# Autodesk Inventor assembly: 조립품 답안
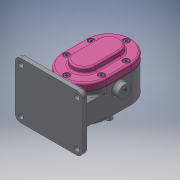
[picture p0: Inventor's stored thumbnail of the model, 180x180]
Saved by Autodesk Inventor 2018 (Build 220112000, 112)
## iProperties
Created: 2020-09
Part Number: 조립품 답안
Document SubType Name: Assembly
Designer: Administrator
Author: Administrator
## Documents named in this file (11)
- C:\Users\Administrator\Desktop\700906V1053\조립품 답안.iam
- C:\Users\Administrator\Desktop\700906V1053\본체.ipt
- C:\Users\Administrator\Desktop\700906V1053\메인축.ipt
- C:\Users\Administrator\Desktop\700906V1053\키 6 x 6 x 18.ipt
- C:\Users\Administrator\Desktop\700906V1053\베어링부시.ipt
- C:\Users\Administrator\Desktop\700906V1053\스퍼기어.ipt
- C:\Users\Administrator\Desktop\700906V1053\오일 실 16 28 7.ipt
- C:\Users\Administrator\Desktop\700906V1053\서브축.ipt
- C:\Users\Administrator\Desktop\700906V1053\개스킷.ipt
- C:\Users\Administrator\Desktop\700906V1053\커버.ipt
- C:\Users\Administrator\Desktop\700906V1053\볼트 M5.ipt
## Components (1 placed, 1 different names)
1. 개스킷:1
